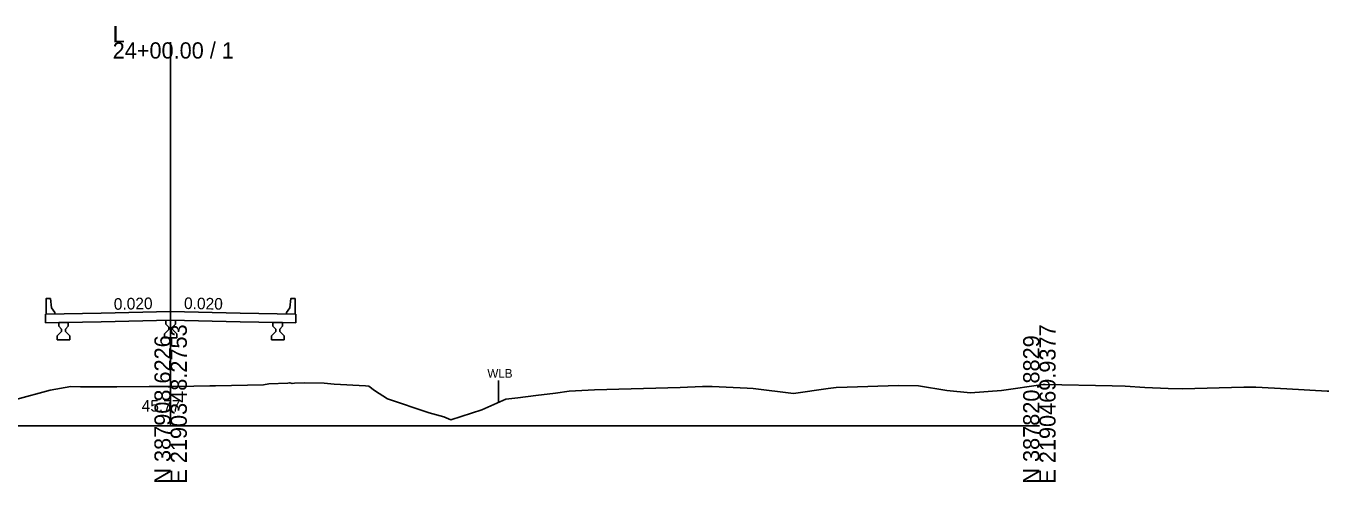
# Model space of a CAD drawing. Extents: x -26 to 2190750, y -10 to 388496.
# Drawn here: x 175 to 400, y 7990.3 to 8069 of the extents above; entities that cross this region are included whole.
import ezdxf

# ---------------------------------------------------------------- set-up
doc = ezdxf.new("R2010")
doc.units = 0
for name, color, linetype in [('Exist Cross Section Cell', 7, 'Continuous'), ('Exist XS Center Line Elevation Label', 7, 'Continuous'), ('Exist XS Ground Line', 7, 'Continuous'), ('Prop CMT Concrete Structures', 7, 'Continuous'), ('Prop RDY Alternate Text Blue', 7, 'Continuous'), ('Prop XS SE Text', 7, 'Continuous')]:
    doc.layers.add(name, color=color, linetype=linetype)

msp = doc.modelspace()

# ---------------------------------------------------------------- linework, layer by layer
at = {"layer": 'Exist Cross Section Cell'}
for p, q in [((200, 8000), (200, 8066.15)), ((50, 8000), (200, 8000)), ((200, 8000), (350, 8000))]:
    msp.add_line(p, q, dxfattribs=at)
at = {"layer": 'Exist XS Ground Line'}
msp.add_lwpolyline([(173.29, 8004.54), (179.2, 8006.12), (182.78, 8006.75), (184.46, 8006.73), (185.9, 8006.74), (190.74, 8006.71), (196.3, 8006.75), (198.2, 8006.75), (200, 8006.77), (204, 8006.81), (206.76, 8006.87), (207.74, 8006.89), (216.01, 8007.07), (216.96, 8007.21), (220.25, 8007.35), (220.57, 8007.42), (220.98, 8007.28), (221.41, 8007.37), (223.15, 8007.38), (226.51, 8007.33), (228.23, 8007.19), (233.63, 8006.91), (234.25, 8006.82), (235.21, 8006.06), (237.43, 8004.65), (244.64, 8002.24), (247.17, 8001.52), (248.4, 8001), (253.74, 8002.74), (257.88, 8004.56), (259.94, 8004.82), (263.08, 8005.2), (266.48, 8005.62), (268.82, 8005.98), (273.16, 8006.17), (287.98, 8006.62), (291.81, 8006.75), (292.99, 8006.77), (293.51, 8006.78), (299.54, 8006.48), (300.56, 8006.42), (307.54, 8005.56), (313.54, 8006.43), (314.9, 8006.62), (316.8, 8006.68), (325.7, 8006.94), (329.14, 8006.91), (334.03, 8006.1), (338.12, 8005.66), (343.44, 8006.1), (350.63, 8007.11), (351, 8007.12), (362.55, 8006.9), (364.83, 8006.8), (368.21, 8006.57), (372.25, 8006.43), (374.74, 8006.34), (385.32, 8006.64), (386.45, 8006.67), (387.35, 8006.64), (392.72, 8006.35), (399.67, 8005.99), (400, 8005.98)], dxfattribs=at)
at = {"layer": 'Prop CMT Concrete Structures'}
for points in [[(180, 8019.29), (180, 8019.54), (179.42, 8020.35), (179.25, 8021.93), (178.5, 8021.93), (178.5, 8019.26)], [(220, 8019.29), (220, 8019.54), (220.58, 8020.35), (220.75, 8021.93), (221.5, 8021.93), (221.5, 8019.26)], [(200, 8019.69), (188, 8019.45), (178.38, 8019.26)], [(178.38, 8019.26), (178.38, 8017.76)], [(178.38, 8017.76), (188, 8017.95), (200, 8018.19)], [(178.5, 8019.26), (180, 8019.29)], [(182.33, 8017.84), (181.5, 8017.82), (180.67, 8017.81)], [(180.67, 8017.81), (180.67, 8017.16)], [(182.33, 8017.16), (182.33, 8017.84)], [(200, 8018.19), (199.17, 8018.18)], [(199.17, 8018.18), (199.17, 8017.53)], [(200, 8018.19), (200, 8019.69)], [(200, 8019.69), (212, 8019.45), (221.63, 8019.26)], [(221.63, 8017.76), (212, 8017.95), (200, 8018.19)], [(200, 8018.19), (200.83, 8018.18)], [(200.83, 8018.18), (200.83, 8017.53)], [(217.67, 8017.84), (218.5, 8017.82), (219.33, 8017.81)], [(217.67, 8017.16), (217.67, 8017.84)], [(219.33, 8017.81), (219.33, 8017.16)], [(221.5, 8019.26), (220, 8019.29)], [(221.63, 8019.26), (221.63, 8017.76)], [(181.17, 8016.24), (180.42, 8015.49)], [(180.42, 8015.49), (180.42, 8014.82)], [(180.67, 8017.16), (181.17, 8016.66)], [(181.17, 8016.66), (181.17, 8016.24)], [(181.83, 8016.66), (182.33, 8017.16)], [(181.83, 8016.24), (181.83, 8016.66)], [(182.58, 8015.49), (181.83, 8016.24)], [(182.58, 8014.82), (182.58, 8015.49)], [(199.67, 8016.61), (198.92, 8015.86)], [(198.92, 8015.86), (198.92, 8015.19)], [(199.17, 8017.53), (199.67, 8017.03)], [(199.67, 8017.03), (199.67, 8016.61)], [(200.83, 8017.53), (200.33, 8017.03)], [(200.33, 8017.03), (200.33, 8016.61)], [(200.33, 8016.61), (201.08, 8015.86)], [(201.08, 8015.86), (201.08, 8015.19)], [(217.42, 8015.49), (218.17, 8016.24)], [(217.42, 8014.82), (217.42, 8015.49)], [(218.17, 8016.66), (217.67, 8017.16)], [(218.17, 8016.24), (218.17, 8016.66)], [(219.33, 8017.16), (218.83, 8016.66)], [(218.83, 8016.66), (218.83, 8016.24)], [(218.83, 8016.24), (219.58, 8015.49)], [(219.58, 8015.49), (219.58, 8014.82)], [(180.42, 8014.82), (181.5, 8014.82), (182.58, 8014.82)], [(198.92, 8015.19), (200, 8015.19)], [(201.08, 8015.19), (200, 8015.19)], [(219.58, 8014.82), (218.5, 8014.82), (217.42, 8014.82)]]:
    msp.add_lwpolyline(points, dxfattribs=at)
at = {"layer": 'Prop RDY Alternate Text Blue'}
msp.add_line((256.61, 8007.82), (256.61, 8004), dxfattribs=at)

# ---------------------------------------------------------------- texts
at = {"layer": 'Exist Cross Section Cell'}
for s, p in [('L', (190, 8066.15)), ('24+00.00 / 1', (190, 8063.35))]:
    msp.add_text(s, height=2.8, dxfattribs=at).set_placement(p)
for s, p in [('N 387908.6226', (200, 7990)), ('E 2190348.2753', (202.8, 7990)), ('N 387820.8829', (350, 7990)), ('E 2190469.9377', (352.8, 7990))]:
    msp.add_text(s, height=2.8, rotation=90, dxfattribs=at).set_placement(p)
at = {"layer": 'Exist XS Center Line Elevation Label'}
msp.add_text('45.77', height=2, dxfattribs=at).set_placement((195, 8002.44))
at = {"layer": 'Prop RDY Alternate Text Blue'}
msp.add_text('WLB', height=1.5, dxfattribs=at).set_placement((254.69, 8008.28))
at = {"layer": 'Prop XS SE Text'}
for rotation, p in [(1.1458, (190.21, 8020)), (358.8542, (202.3, 8020.15))]:
    msp.add_text('0.020', height=2, rotation=rotation, dxfattribs=at).set_placement(p)

doc.saveas('drawing.dxf')
